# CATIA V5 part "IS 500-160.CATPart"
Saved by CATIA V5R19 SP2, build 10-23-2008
Part number: IS 500-160
Bounding box of the stored display mesh (mm): x -22.494 to 22.494, y -22.494 to 22.494, z 0 to 405
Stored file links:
  C:\Users\Bora\Desktop\3D Katı model\IS serisi\IS 500\IS 500-160.CATPart
  C:\Program Files\Dassault Systemes\B19\intel_a\reffiles\standard\MetricThickPitch.txt
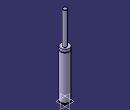
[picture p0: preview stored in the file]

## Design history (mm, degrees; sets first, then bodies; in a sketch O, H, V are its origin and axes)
Body1 (main body)
  Sketch1 on yz-plane, origin (0, 0, 0), H (0, 1, 0), V (0, 0, 1)
    point P3 (10, 404)
    point P5 (10, 404)
    point P7 (22.5, 229.5)
    point P8 (22.5, 227.5)
    point P12 (22.5, 227.5)
    point P13 (22.5, 229.5)
    line L1 (22.5, 0) -> (22.5, 4)
    line L2 (10, 404) -> (10, 243)
    arc A1 centre (9, 404) radius 1 from (10, 404) to (9, 405) ccw
    arc A2 centre (22.5, 228.5) radius 1 from (22.5, 229.5) to (22.5, 227.5) ccw
    line L3 (20, 7.5) -> (20, 4)
    line L4 (22.5, 7.5) -> (22.5, 227.5)
    line L5 (22.5, 229.5) -> (22.5, 243)
    line L6 (9, 405) -> (0, 405)
    point P15 (0, 405)
    line L7 (10, 243) -> (22.5, 243)
    line L8 (20, 7.5) -> (22.5, 7.5)
    line L9 (20, 4) -> (22.5, 4)
    line L10 (22.5, 0) -> (0, 0)
    coincidence: P15 V, P3 P5, P7 P13, P8 P12
    tangency: L6 A1
    horizontal: L7 H, L8 H, L9 H, L10 H
  Shaft1: profile Sketch1, axis Sketch1.V, angle 360
  Sketch2 on face of Shaft1 from Sketch1.L10, origin (0, 0, 0), H (1, 0, 0), V (0, -1, 0)
    point P1 (10, 0)
    distance P1 V = 10
  Hole1: placed by Sketch2, at (10, 0, 0) direction (0, 0, 1), diameter 6.647, depth 13, threaded "M8", thread diameter 8, thread depth 13, pitch 1.25
  Sketch3 on face of Shaft1 from Sketch1.L10, origin (0, 0, 0), H (1, 0, 0), V (0, -1, 0)
    point P1 (-10, 0)
    distance P1 V = 10
  Hole2: placed by Sketch3, at (-10, 0, 0) direction (0, 0, 1), diameter 6.647, depth 13, threaded "M8", thread diameter 8, thread depth 13, pitch 1.25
